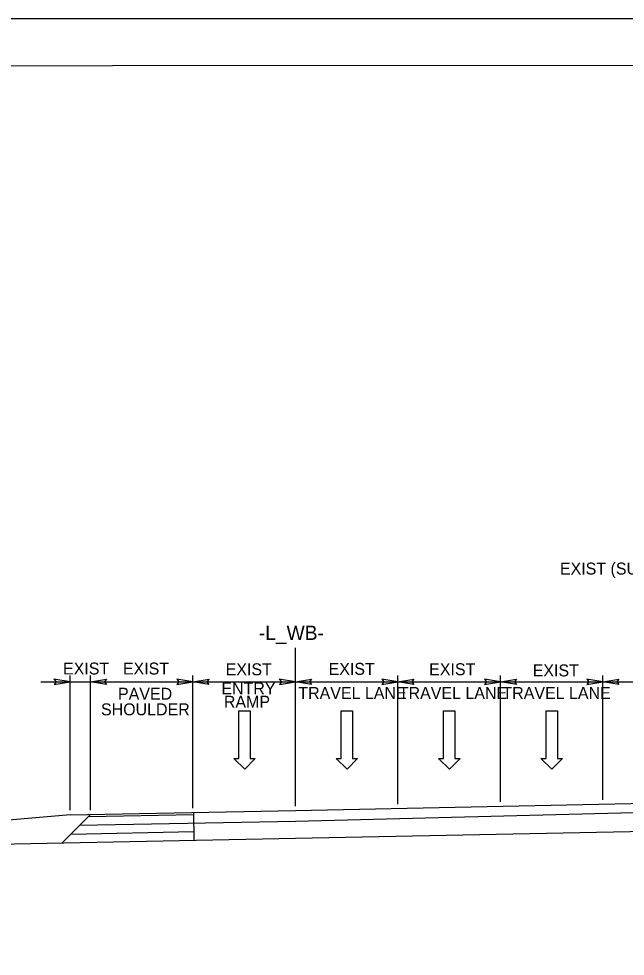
# Model space of a CAD drawing. Extents: x 1726790 to 1728895, y 539219 to 541550.
# Drawn here: x 1727358.1 to 1727429.2, y 539492.3 to 539602.3 of the extents above; entities that cross this region are included whole.
import ezdxf

# ---------------------------------------------------------------- set-up
doc = ezdxf.new("R2010")
doc.units = 0
for name, color, linetype in [('Default', 7, 'Continuous'), ('Overhead Sheet Border', 7, 'Continuous'), ('Sheet Plot Border Outside CELL', 7, 'Continuous'), ('Typical Pavement Slope CELL', 7, 'Continuous'), ('Typical Pavement Slope Information CELL', 7, 'Continuous'), ('Typical Text Centerline CELL', 7, 'Continuous')]:
    doc.layers.add(name, color=color, linetype=linetype)

msp = doc.modelspace()

# ---------------------------------------------------------------- linework, layer by layer
at = {"layer": 'Default'}
for p, q in [((1727390.49, 539509.92), (1727390.49, 539528.5)), ((1727360.62, 539524.49), (1727366.49, 539524.49)), ((1727364.07, 539509.44), (1727364.07, 539525.23)), ((1727366.47, 539509.44), (1727366.47, 539525.23)), ((1727366.47, 539509.44), (1727366.47, 539524.99)), ((1727366.49, 539524.49), (1727378.5, 539524.49)), ((1727378.48, 539509.68), (1727378.48, 539525.23)), ((1727378.5, 539524.49), (1727390.51, 539524.49)), ((1727390.49, 539509.92), (1727390.49, 539525.23)), ((1727390.51, 539524.49), (1727402.52, 539524.49)), ((1727402.49, 539510.16), (1727402.49, 539525.23)), ((1727402.52, 539524.49), (1727414.53, 539524.49)), ((1727414.53, 539510.4), (1727414.53, 539525.23)), ((1727414.53, 539524.49), (1727426.53, 539524.49)), ((1727426.53, 539510.64), (1727426.53, 539525.23)), ((1727426.53, 539524.49), (1727437.33, 539524.49)), ((1727383.86, 539515.51), (1727383.86, 539521.11)), ((1727383.86, 539521.11), (1727385.18, 539521.11)), ((1727385.18, 539521.11), (1727385.18, 539515.51)), ((1727395.86, 539515.51), (1727395.86, 539521.11)), ((1727395.86, 539521.11), (1727397.18, 539521.11)), ((1727397.18, 539521.11), (1727397.18, 539515.51)), ((1727407.87, 539515.51), (1727407.87, 539521.11)), ((1727407.87, 539521.11), (1727409.19, 539521.11)), ((1727409.19, 539521.11), (1727409.19, 539515.51)), ((1727419.88, 539515.51), (1727419.88, 539521.11)), ((1727419.88, 539521.11), (1727421.2, 539521.11)), ((1727421.2, 539521.11), (1727421.2, 539515.51)), ((1727384.54, 539514.25), (1727383.26, 539515.51)), ((1727383.26, 539515.51), (1727383.86, 539515.51)), ((1727385.78, 539515.51), (1727384.54, 539514.25)), ((1727385.18, 539515.51), (1727385.78, 539515.51)), ((1727396.54, 539514.25), (1727395.26, 539515.51)), ((1727395.26, 539515.51), (1727395.86, 539515.51)), ((1727397.78, 539515.51), (1727396.54, 539514.25)), ((1727397.18, 539515.51), (1727397.78, 539515.51)), ((1727408.55, 539514.25), (1727407.27, 539515.51)), ((1727407.27, 539515.51), (1727407.87, 539515.51)), ((1727409.79, 539515.51), (1727408.55, 539514.25)), ((1727409.19, 539515.51), (1727409.79, 539515.51)), ((1727420.56, 539514.25), (1727419.28, 539515.51)), ((1727419.28, 539515.51), (1727419.88, 539515.51)), ((1727421.8, 539515.51), (1727420.56, 539514.25)), ((1727421.2, 539515.51), (1727421.8, 539515.51))]:
    msp.add_line(p, q, dxfattribs=at)
for points in [[(1727362.19, 539524.17), (1727364.07, 539524.49), (1727362.18, 539524.83), (1727362.42, 539524.49)], [(1727368.34, 539524.17), (1727366.47, 539524.49), (1727368.35, 539524.83), (1727368.11, 539524.49)], [(1727376.6, 539524.17), (1727378.48, 539524.49), (1727376.59, 539524.83), (1727376.83, 539524.49)], [(1727380.35, 539524.17), (1727378.48, 539524.49), (1727380.36, 539524.83), (1727380.12, 539524.49)], [(1727388.61, 539524.17), (1727390.49, 539524.49), (1727388.6, 539524.83), (1727388.84, 539524.49)], [(1727392.36, 539524.17), (1727390.49, 539524.49), (1727392.37, 539524.83), (1727392.13, 539524.49)], [(1727400.62, 539524.17), (1727402.49, 539524.49), (1727400.61, 539524.83), (1727400.85, 539524.49)], [(1727404.37, 539524.17), (1727402.49, 539524.49), (1727404.38, 539524.83), (1727404.14, 539524.49)], [(1727412.65, 539524.17), (1727414.53, 539524.49), (1727412.64, 539524.83), (1727412.88, 539524.49)], [(1727416.4, 539524.17), (1727414.53, 539524.49), (1727416.41, 539524.83), (1727416.17, 539524.49)], [(1727424.66, 539524.17), (1727426.53, 539524.49), (1727424.65, 539524.83), (1727424.89, 539524.49)], [(1727428.41, 539524.17), (1727426.53, 539524.49), (1727428.42, 539524.83), (1727428.18, 539524.49)]]:
    msp.add_lwpolyline(points, close=True, dxfattribs=at)
at = {"layer": 'Overhead Sheet Border'}
msp.add_lwpolyline([(1727593.82, 539596.91), (1727294.08, 539596.75), (1727294.19, 539386.93), (1727593.93, 539387.09)], close=True, dxfattribs=at)
at = {"layer": 'Sheet Plot Border Outside CELL'}
msp.add_lwpolyline([(1727598.07, 539602.3), (1727261.51, 539602.3), (1727261.51, 539383.13), (1727598.07, 539383.13)], close=True, dxfattribs=at)
at = {"layer": 'Typical Pavement Slope CELL'}
for p, q in [((1727390.49, 539509.42), (1727437.33, 539510.36)), ((1727364.07, 539508.89), (1727390.48, 539509.42)), ((1727378.53, 539509.18), (1727378.59, 539505.93)), ((1727390.49, 539508.17), (1727437.33, 539509.34)), ((1727364.07, 539508.89), (1727321.18, 539505.14)), ((1727366.47, 539508.94), (1727363.15, 539505.62)), ((1727365.19, 539507.67), (1727390.49, 539508.17)), ((1727366.21, 539508.69), (1727378.53, 539508.93)), ((1727364.17, 539506.64), (1727378.57, 539506.93)), ((1727390.49, 539506.17), (1727437.33, 539507.11)), ((1727322.16, 539504.8), (1727390.49, 539506.17))]:
    msp.add_line(p, q, dxfattribs=at)

# ---------------------------------------------------------------- texts
at = {"layer": 'Typical Pavement Slope Information CELL'}
for s, p in [('EXIST (SUPPORT)', (1727421.5, 539537.09)), ('EXIST', (1727363.24, 539525.36)), ('EXIST', (1727370.26, 539525.36)), ('EXIST', (1727382.31, 539525.27)), ('EXIST', (1727394.38, 539525.32)), ('EXIST', (1727406.17, 539525.28)), ('EXIST', (1727418.31, 539525.14)), ('ENTRY', (1727381.81, 539523.03)), ('PAVED', (1727369.69, 539522.4)), ('TRAVEL LANE', (1727390.83, 539522.49)), ('TRAVEL LANE', (1727402.61, 539522.49)), ('TRAVEL LANE', (1727414.76, 539522.49)), ('RAMP', (1727382.1, 539521.46)), ('SHOULDER', (1727367.69, 539520.57))]:
    msp.add_text(s, height=1.401, dxfattribs=at).set_placement(p)
at = {"layer": 'Typical Text Centerline CELL'}
msp.add_text('-L_WB-', height=1.684, dxfattribs=at).set_placement((1727386.2, 539529.41))

doc.saveas('drawing.dxf')
